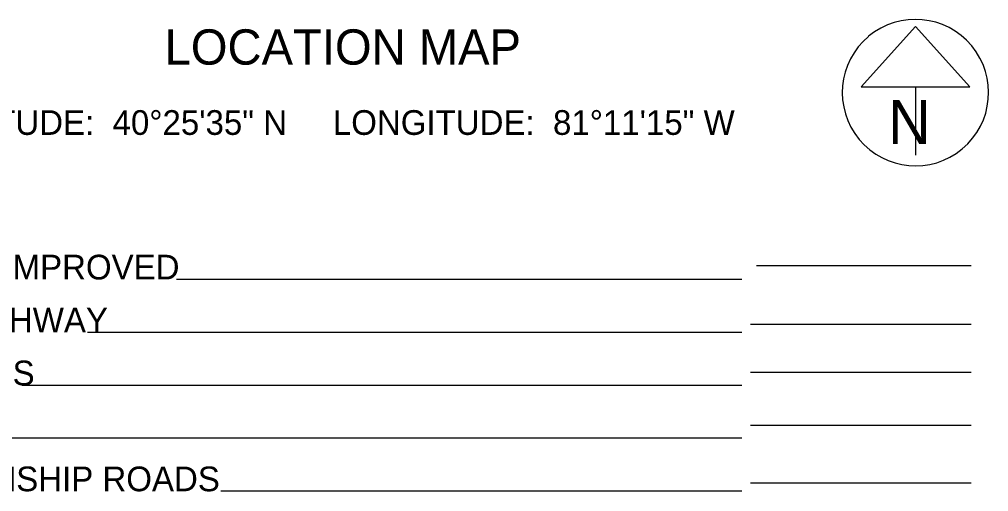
# Model space of a CAD drawing. Extents: x 0 to 34, y 0 to 22.
# Drawn here: x 3.6 to 9.1, y 11.17 to 13.85 of the extents above; entities that cross this region are included whole.
import ezdxf

# ---------------------------------------------------------------- set-up
doc = ezdxf.new("R2010")
doc.units = 0
doc.layers.add('SH_Data', color=7, linetype='Continuous')
doc.layers.add('SH_Text', color=7, linetype='Continuous')

msp = doc.modelspace()

# ---------------------------------------------------------------- linework, layer by layer
at = {"layer": 'SH_Data'}
for p, q in [((8.6845, 13.809), (8.3769, 13.4678)), ((8.9921, 13.4678), (8.6845, 13.809)), ((8.3769, 13.4678), (8.9921, 13.4678)), ((8.6845, 13.4678), (8.6845, 13.081)), ((8.6845, 13.4353), (8.6845, 13.4353)), ((8.6845, 13.4353), (8.6845, 13.4353)), ((7.7827, 12.4553), (9, 12.4553)), ((7.7827, 12.4553), (9, 12.4553)), ((7.7, 12.3767), (4.4937, 12.3767)), ((7.7, 12.3767), (4.4937, 12.3767)), ((9, 12.1207), (7.75, 12.1207)), ((9, 12.1207), (7.75, 12.1207)), ((7.7, 12.0767), (3.9895, 12.0767)), ((7.7, 12.0767), (3.9895, 12.0767)), ((9, 11.8491), (7.75, 11.8491)), ((9, 11.8491), (7.75, 11.8491)), ((7.7, 11.7767), (3.6192, 11.7767)), ((7.7, 11.7767), (3.6192, 11.7767)), ((9, 11.5491), (7.75, 11.5491)), ((9, 11.5491), (7.75, 11.5491)), ((7.7, 11.4767), (3.3288, 11.4767)), ((7.7, 11.4767), (3.3288, 11.4767)), ((9, 11.2223), (7.75, 11.2223)), ((9, 11.2223), (7.75, 11.2223)), ((7.7, 11.1767), (4.7452, 11.1767)), ((7.7, 11.1767), (4.7452, 11.1767))]:
    msp.add_line(p, q, dxfattribs=at)
msp.add_arc((8.6845, 13.4353), 0.4148, 129.7798, 129.7633, dxfattribs=at)

# ---------------------------------------------------------------- texts
msp.add_text('N', height=0.25, dxfattribs=at).set_placement((8.5292, 13.1439))
at = {"layer": 'SH_Text'}
for s, height, p in [('LOCATION MAP', 0.2, (4.4269, 13.5937)), ('LATITUDE:  40°25\'35" N     LONGITUDE:  81°11\'15" W', 0.14, (3.071, 13.1958)), ('PORTION TO BE IMPROVED', 0.14, (1.9944, 12.3767)), ('PORTION TO BE IMPROVED', 0.14, (1.9944, 12.3767)), ('INTERSTATE HIGHWAY', 0.14, (1.9944, 12.0767)), ('INTERSTATE HIGHWAY', 0.14, (1.9944, 12.0767)), ('FEDERAL ROUTES', 0.14, (1.9944, 11.7767)), ('FEDERAL ROUTES', 0.14, (1.9944, 11.7767)), ('COUNTY & TOWNSHIP ROADS', 0.14, (1.9944, 11.1767)), ('COUNTY & TOWNSHIP ROADS', 0.14, (1.9944, 11.1767))]:
    msp.add_text(s, height=height, dxfattribs=at).set_placement(p)

doc.saveas('drawing.dxf')
